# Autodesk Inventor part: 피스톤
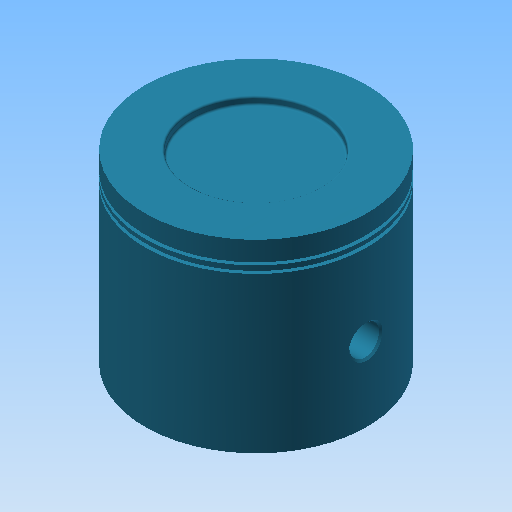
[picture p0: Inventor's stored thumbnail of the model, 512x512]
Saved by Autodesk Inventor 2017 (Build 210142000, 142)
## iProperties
Created: 2016-11
Part Number: 피스톤
Material: 강철, 탄소
Document SubType Name: Modeling
Designer: mduedu
Density: 7.87 g/cm^3
Mass: 410.154 g
Surface Area: 237.492 cm^2
Volume: 52.1161 cm^3
Appearance: 터키옥색
Author: mduedu
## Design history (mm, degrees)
sketch "스케치1"
  geometry: C1 r 30 at (0, 0); 1 further point
  constraints: 1 centre point, 1 coincident
  dimensions: "d0" = 60 diameter of C1
extrude "돌출1" new body sketch "스케치1" distance "d1" = 50; taper "d2" = 0 deg
sketch "스케치2"
  geometry: C1 r 28 at (0, 0); 1 further point
  constraints: 1 centre point, 1 coincident
  dimensions: "d3" = 56 diameter of C1
extrude "돌출2" cut sketch "스케치2" distance "d4" = 45; taper "d5" = 0 deg
sketch "스케치3"
  geometry: L1 (30, 0)-(30, 50) reference; L2 (30, 45)-(29, 45); L3 (29, 45)-(29, 44); L4 (29, 44)-(30, 44); L5 (30, 44)-(30, 45); L6 (30, 43)-(29, 43); L7 (29, 43)-(29, 42); L8 (29, 42)-(30, 42); L9 (30, 42)-(30, 43); L10 (30, 50)-(-30, 50) reference; L11 (0, 50)-(0, 0)
  constraints: 18 end point, 4 parallel, 3 equal length, 3 perpendicular, 2 horizontal, 2 point on line, 1 midpoint
  dimensions: "d6" = 1 distance of L2.start L2.end; "d8" = 5 distance between parallel lines of L10 L2; "d9" = 1 distance between parallel lines of L6 L4
revolve "회전1" sketch "스케치3" stored, may be unused: angle "d10" = 90 deg
node "작업 평면1"
sketch "스케치4"
  geometry: L1 (0, -22.978)-(45, -22.978) reference; L2 (45, -22.978)-(45, 22.978) reference; L3 (45, 22.978)-(0, 22.978) reference; L4 (0, 22.978)-(0, 25.377) reference; L5 (0, 25.377)-(42, 25.377) reference; L6 (42, 25.377)-(42, 24.187) reference; L7 (42, 24.187)-(43, 24.187) reference; L8 (43, 24.187)-(43, 25.377) reference; L9 (43, 25.377)-(44, 25.377) reference; L10 (44, 25.377)-(44, 24.187) reference; L11 (44, 24.187)-(45, 24.187) reference; L12 (45, 24.187)-(45, 25.377) reference; L13 (45, 25.377)-(50, 25.377) reference; L14 (50, 25.377)-(50, -25.377) reference; L15 (50, -25.377)-(45, -25.377) reference; L16 (45, -25.377)-(45, -24.187) reference; L17 (45, -24.187)-(44, -24.187) reference; L18 (44, -24.187)-(44, -25.377) reference; L19 (44, -25.377)-(43, -25.377) reference; L20 (43, -25.377)-(43, -24.187) reference; L21 (43, -24.187)-(42, -24.187) reference; L22 (42, -24.187)-(42, -25.377) reference; L23 (42, -25.377)-(0, -25.377) reference; L24 (0, -25.377)-(0, -22.978) reference; L25 (12.5, 22.978)-(45, 22.978); L26 (45, 22.978)-(45, -22.978); L27 (45, -22.978)-(12.5, -22.978); L28 (12.5, -22.978)-(12.5, 22.978); C1 r 7.5 at (20, 0); C2 r 4 at (20, 0); 1 further point
  constraints: 8 end point, 2 centre point, 2 parallel, 1 coincident, 1 horizontal, 1 horizontal alignment, 1 perpendicular, 1 point on line, 1 tangent
  dimensions: "d12" = 15 diameter of C1; "d13" = 8 diameter of C2; "d14" = 20 distance of point (0, 0) C1.centre
  node "절단 모서리 투영1"
extrude "돌출3" join sketch "스케치4" stored distance "d15" = 11.75; taper "d16" = 0 deg
extrude "돌출4" cut sketch "스케치4" stored distance "d17" = 72; taper "d18" = 0 deg
fillet "모깎기2" dims "d20" = 3
chamfer "모따기1" distance "d21" = 0.5; stored, may be unused: second distance "d22" = 2, angle "d23" = 45 deg
chamfer "모따기2" distance "d24" = 0.5; stored, may be unused: second distance "d25" = 2, angle "d26" = 45 deg
sketch "스케치5"
  geometry: C1 r 17.5 at (0, 0); 1 further point
  constraints: 1 centre point, 1 coincident
  dimensions: "d27" = 35 diameter of C1
extrude "돌출5" cut sketch "스케치5" distance "d28" = 2; taper "d29" = 0 deg
fillet "모깎기3" dims "d30" = 0.5
node "솔리드1"
mirror "대칭1"
other parameters: "d11" = -16
